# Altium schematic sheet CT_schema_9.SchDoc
size 391 x 238 mm
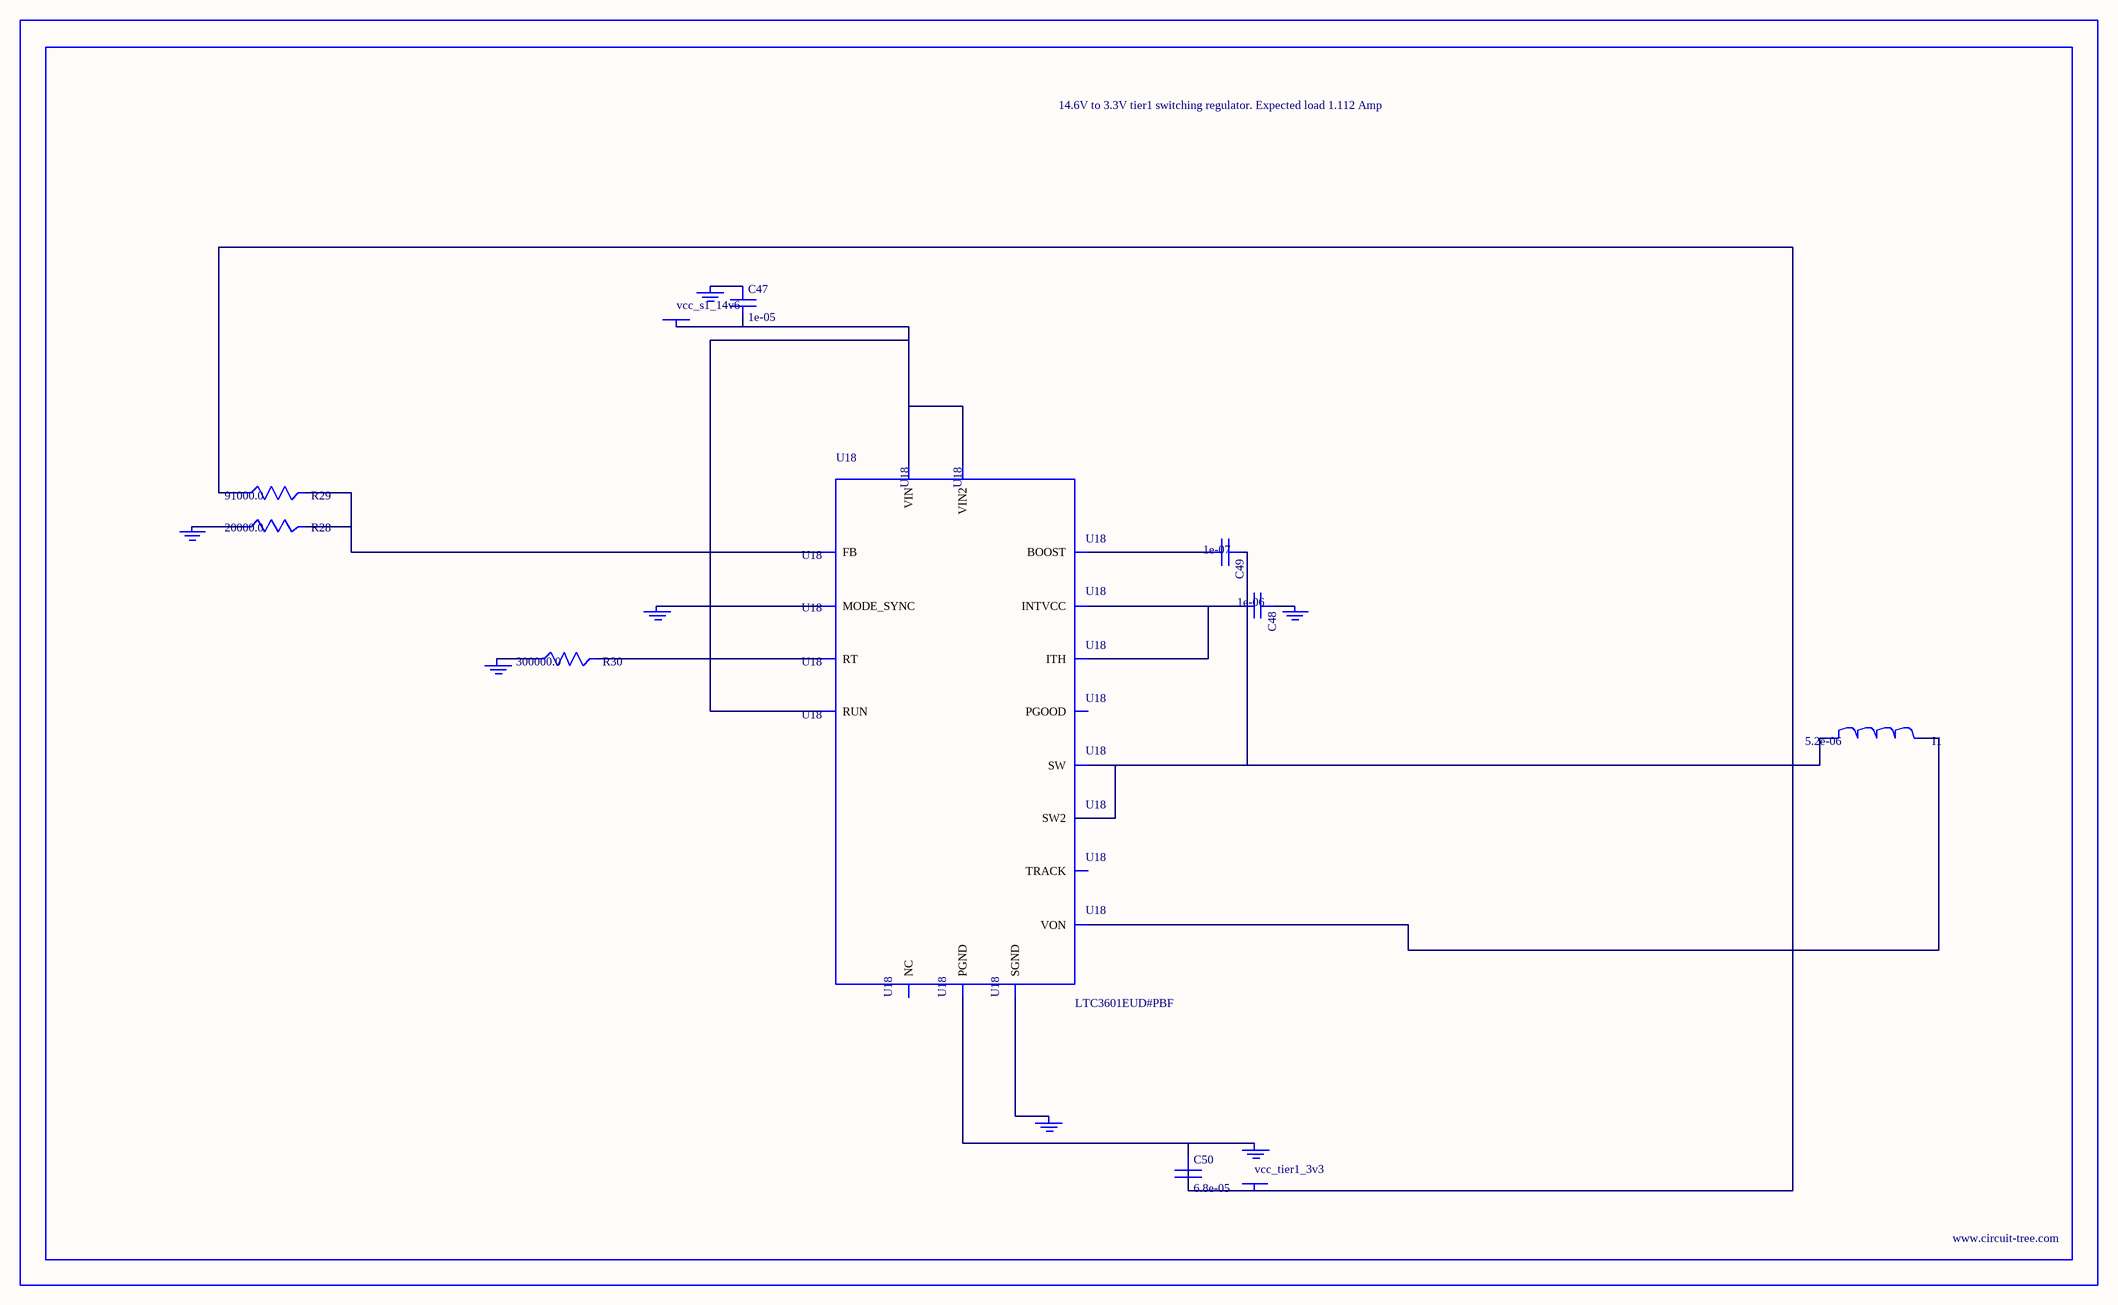
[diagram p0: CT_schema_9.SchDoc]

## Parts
BORDER8  (no value)
C47  1e-05  [C0805]
C48  1e-06  [C0603]
C49  1e-07  [C0402]
C50  6.8e-05  [2220]
GND_INSTANCE_8_0  (no value)
GND_INSTANCE_8_1  (no value)
GND_INSTANCE_8_2  (no value)
GND_INSTANCE_8_3  (no value)
GND_INSTANCE_8_4  (no value)
GND_INSTANCE_8_5  (no value)
GND_INSTANCE_8_6  (no value)
I1  5.2e-06  [DR1040]
POWER_INSTANCE_8_0  vcc_s1_14v6
POWER_INSTANCE_8_1  vcc_tier1_3v3
R28  20000.0  [R0603]
R29  91000.0  [R0603]
R30  300000.0  [R0603]
U18  LTC3601EUD#PBF  [QFN-16_EP]

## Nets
NetC47_1: C47.1 GND_INSTANCE_8_5.0(GND)
NetC47_2: C47.2 POWER_INSTANCE_8_0.0(PWR) U18.14(RUN) U18.15(VIN) U18.16(VIN2)
NetC48_1: C48.1 GND_INSTANCE_8_1.0(GND)
NetC48_2: C48.2 U18.7(INTVCC) U18.12(ITH)
NetC49_1: C49.1 I1.1 U18.3(SW) U18.4(SW2)
NetC49_2: C49.2 U18.6(BOOST)
NetC50_1: C50.1 GND_INSTANCE_8_6.0(GND) U18.17(PGND)
NetC50_2: C50.2 I1.2 POWER_INSTANCE_8_1.0(PWR) R29.1 U18.8(VON)
NetGND_INSTANCE_8_0_0: GND_INSTANCE_8_0.0(GND) U18.1(MODE_SYNC)
NetGND_INSTANCE_8_2_0: GND_INSTANCE_8_2.0(GND) U18.9(SGND)
NetGND_INSTANCE_8_3_0: GND_INSTANCE_8_3.0(GND) R30.1
NetGND_INSTANCE_8_4_0: GND_INSTANCE_8_4.0(GND) R28.1
NetR28_2: R28.2 R29.2 U18.11(FB)
NetR30_2: R30.2 U18.10(RT)

Not connected (* = marked no-connect by the designer): U18 2(PGOOD) 5(NC) 13(TRACK)

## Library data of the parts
BORDER8 = BORDER_PAGE8
C47 = C0805C106K8RACTU
C48 = C0603C105K3RACTU
C49 = C0402C104K3RACTU
C50 = C5750X5R1A686M
GND_INSTANCE_8_0-GND_INSTANCE_8_6 = GND
I1 = DR1040-5R2-R
POWER_INSTANCE_8_0 POWER_INSTANCE_8_1 = PWR
R28 = RC0603JR-0720KL
R29 = RC0603JR-0791KL
R30 = RC0603JR-07300KL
